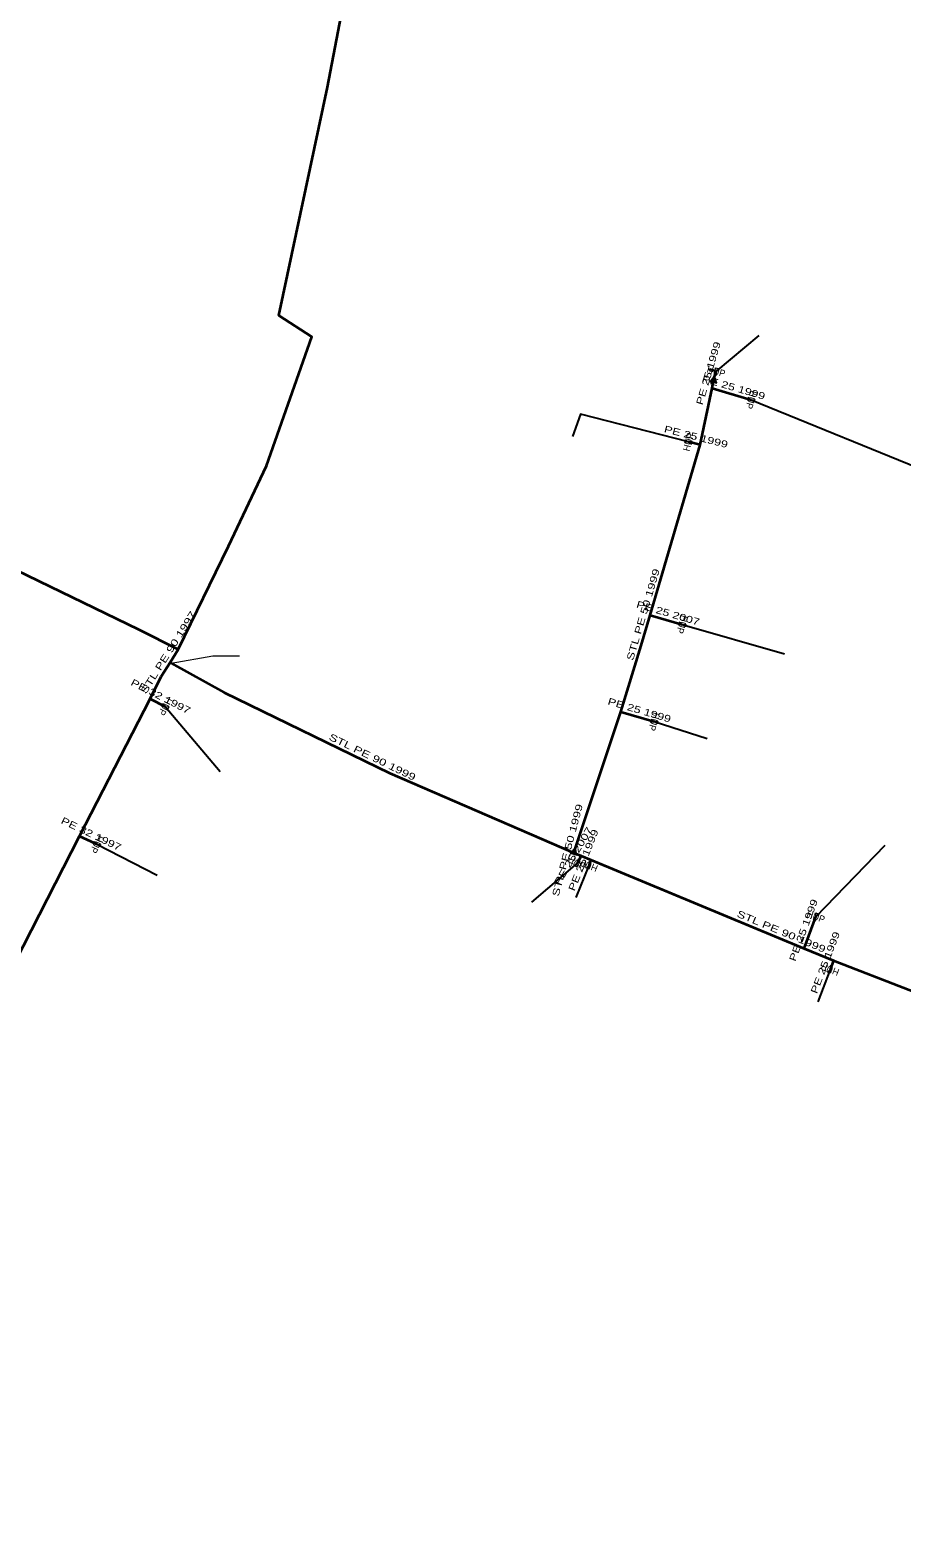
# Model space of a CAD drawing. Extents: x -737484 to -734496, y -1033882 to -1030666.
# Drawn here: x -735749 to -735623.1, y -1032392.5 to -1032174.7 of the extents above; entities that cross this region are included whole.
import ezdxf
from ezdxf.enums import TextEntityAlignment as Align

# ---------------------------------------------------------------- set-up
doc = ezdxf.new("R2010")
doc.units = 0
doc.header["$LTSCALE"] = 0.4
for name, color, linetype, lineweight in [('1', 7, 'Continuous', 13), ('22', 7, 'Continuous', 25), ('5', 7, 'Continuous', 35), ('7', 7, 'Continuous', 35)]:
    doc.layers.add(name, color=color, linetype=linetype, lineweight=lineweight)
doc.layers.add('2', color=7, linetype='Continuous')

msp = doc.modelspace()

# ---------------------------------------------------------------- linework, layer by layer
at = {"layer": '1'}
for p, q in [((-735650.461, -1032223.739), (-735650.797, -1032223.642)), ((-735649.929, -1032223.97), (-735650.409, -1032223.832))]:
    msp.add_line(p, q, dxfattribs=at)
for points in [[(-735649.982, -1032223.432), (-735649.597, -1032223.542), (-735650.258, -1032224.393), (-735649.873, -1032224.503)], [(-735650.89, -1032223.694), (-735650.931, -1032223.838), (-735650.45, -1032223.976), (-735650.409, -1032223.832)], [(-735650.89, -1032223.694), (-735650.848, -1032223.55), (-735650.368, -1032223.687), (-735650.409, -1032223.832)], [(-735650.843, -1032223.669), (-735650.822, -1032223.597), (-735650.414, -1032223.714), (-735650.434, -1032223.786)], [(-735650.833, -1032225.455), (-735649.851, -1032225.646), (-735650.151, -1032224.569)], [(-735649.991, -1032225.517), (-735650.194, -1032224.789), (-735650.655, -1032225.388)], [(-735650.236, -1032225.007), (-735650.477, -1032225.32), (-735650.13, -1032225.388)], [(-735644.322, -1032228.005), (-735644.432, -1032228.39), (-735645.283, -1032227.729), (-735645.393, -1032228.114)], [(-735654.461, -1032234.231), (-735654.364, -1032233.842), (-735653.491, -1032234.473), (-735653.394, -1032234.084)], [(-735654.304, -1032260.465), (-735654.414, -1032260.85), (-735655.265, -1032260.189), (-735655.375, -1032260.574)], [(-735728.947, -1032272.422), (-735729.129, -1032272.779), (-735729.838, -1032271.968), (-735730.02, -1032272.325)], [(-735658.352, -1032274.514), (-735658.462, -1032274.899), (-735659.313, -1032274.238), (-735659.423, -1032274.623)], [(-735738.817, -1032292.304), (-735738.986, -1032292.666), (-735739.723, -1032291.881), (-735739.892, -1032292.243)], [(-735671.002, -1032293.591), (-735670.036, -1032293.85), (-735670.26, -1032292.755)], [(-735670.167, -1032293.711), (-735670.318, -1032292.971), (-735670.82, -1032293.536)], [(-735670.376, -1032293.186), (-735670.637, -1032293.482), (-735670.296, -1032293.573)], [(-735670.096, -1032295.541), (-735670.438, -1032295.335), (-735669.581, -1032294.684), (-735669.923, -1032294.478)], [(-735668.329, -1032295.876), (-735668.7, -1032295.726), (-735667.955, -1032294.949), (-735668.326, -1032294.799)], [(-735635.553, -1032302.21), (-735635.178, -1032302.347), (-735635.895, -1032303.15), (-735635.52, -1032303.287)], [(-735633.47, -1032310.907), (-735633.843, -1032310.764), (-735633.112, -1032309.973), (-735633.485, -1032309.83)]]:
    msp.add_lwpolyline(points, close=True, dxfattribs=at)
msp.add_lwpolyline([(-735728.61, -1032266.12), (-735722.629, -1032265.037), (-735718.739, -1032265.037)], dxfattribs=at)
at = {"layer": '22'}
for p, q in [((-735649.928, -1032223.968), (-735643.699, -1032218.788)), ((-735644.858, -1032228.06), (-735614.219, -1032240.563)), ((-735654.84, -1032260.52), (-735640.05, -1032264.779)), ((-735729.484, -1032272.374), (-735721.568, -1032281.756)), ((-735658.888, -1032274.569), (-735651.24, -1032276.994)), ((-735739.356, -1032292.276), (-735730.638, -1032296.762)), ((-735635.537, -1032302.749), (-735625.538, -1032292.417)), ((-735670.01, -1032295.01), (-735676.59, -1032300.671)), ((-735668.328, -1032295.338), (-735670.179, -1032299.983)), ((-735633.478, -1032310.369), (-735635.26, -1032315.041))]:
    msp.add_line(p, q, dxfattribs=at)
msp.add_lwpolyline([(-735653.929, -1032234.159), (-735669.494, -1032230.143), (-735670.665, -1032233.365)], dxfattribs=at)
at = {"layer": '5'}
for p, q in [((-735728.779, -1032266.028), (-735727.61, -1032264.16)), ((-735670.47, -1032293.54), (-735670.39, -1032293.238))]:
    msp.add_line(p, q, dxfattribs=at)
for points in [[(-735727.61, -1032264.16), (-735720.34, -1032249.21), (-735714.85, -1032237.63), (-735708.3, -1032218.96), (-735713.1, -1032215.9), (-735706.04, -1032182.91), (-735701.19, -1032157.47), (-735702.91, -1032152.78), (-735705.8, -1032151.16), (-735736.55, -1032141.95), (-735730.97, -1032118.51), (-735729.04, -1032111.89), (-735727.47, -1032106.8), (-735722.56, -1032083.87), (-735720.82, -1032078.73), (-735717.39, -1032078.97), (-735716.966, -1032077.63)], [(-735727.61, -1032264.16), (-735733.24, -1032261.3), (-735754.23, -1032251.12), (-735765.52, -1032245.22), (-735795.64, -1032232.38), (-735827.69, -1032218.06), (-735828.419, -1032217.899)], [(-735670.39, -1032293.238), (-735663.69, -1032273.16), (-735660.75, -1032263.59), (-735659.45, -1032259.17), (-735652.22, -1032234.59), (-735650.52, -1032226.4), (-735650.247, -1032225.06)], [(-735815.73, -1032430.9), (-735815.43, -1032430.06), (-735811.41, -1032422.83), (-735808.66, -1032417.37), (-735805.75, -1032411.37), (-735798.98, -1032396.22), (-735796.46, -1032389.94), (-735789.36, -1032374.09), (-735787.3, -1032370.19), (-735782.93, -1032362.57), (-735779.46, -1032355.93), (-735774.32, -1032348.37), (-735768.24, -1032342.42), (-735754.62, -1032316.01), (-735741.84, -1032291.1), (-735731.68, -1032271.26), (-735730.05, -1032268.06), (-735728.779, -1032266.028)], [(-735728.779, -1032266.028), (-735728.61, -1032266.12), (-735720.98, -1032270.37), (-735697.03, -1032282.03), (-735670.47, -1032293.54)], [(-735670.47, -1032293.54), (-735669.395, -1032293.967), (-735668.01, -1032294.54), (-735637.23, -1032307.33), (-735632.99, -1032309.09), (-735611.11, -1032317.53)]]:
    msp.add_lwpolyline(points, dxfattribs=at)
at = {"layer": '7'}
for p, q in [((-735650.247, -1032225.06), (-735649.928, -1032223.968)), ((-735650.52, -1032226.4), (-735644.858, -1032228.06)), ((-735652.22, -1032234.59), (-735653.928, -1032234.158)), ((-735659.45, -1032259.17), (-735654.84, -1032260.52)), ((-735731.68, -1032271.26), (-735729.484, -1032272.374)), ((-735663.69, -1032273.16), (-735658.888, -1032274.569)), ((-735669.395, -1032293.967), (-735670.01, -1032295.01)), ((-735668.01, -1032294.54), (-735668.328, -1032295.338)), ((-735637.23, -1032307.33), (-735635.537, -1032302.749)), ((-735632.99, -1032309.09), (-735633.478, -1032310.369))]:
    msp.add_line(p, q, dxfattribs=at)
msp.add_lwpolyline([(-735741.84, -1032291.1), (-735740.29, -1032291.84), (-735739.355, -1032292.274)], dxfattribs=at)

# ---------------------------------------------------------------- texts
at = {"layer": '2', "width": 0.95}
for rotation, p in [(344, (-735650.0653, -1032224.4478)), (254, (-735645.3378, -1032227.9217)), (76, (-735653.442, -1032234.2785)), (254, (-735655.3198, -1032260.3817)), (243, (-735729.9295, -1032272.1465)), (254, (-735659.3678, -1032274.4307)), (245, (-735739.8076, -1032292.0622)), (149, (-735669.752, -1032294.5808)), (158, (-735668.1402, -1032294.874)), (340, (-735635.7075, -1032303.2187)), (159, (-735633.2983, -1032309.9017))]:
    msp.add_text('HUP', height=1, rotation=rotation, dxfattribs=at).set_placement(p, align=Align.CENTER)
at = {"layer": '5', "width": 1.4}
for s, rotation, p in [('STL PE 50 1999', 73.61, (-735659.9901, -1032259.2356)), ('STL PE 90 1997', 57.962, (-735728.6178, -1032264.8282)), ('STL PE 90 1999', 334.041, (-735699.7854, -1032280.1321)), ('STL PE 50 1999', 75.163, (-735670.9131, -1032293.26)), ('STL PE 90 1999', 337.436, (-735640.7059, -1032305.3439))]:
    msp.add_text(s, height=1, rotation=rotation, dxfattribs=at).set_placement(p, align=Align.CENTER)
at = {"layer": '7', "width": 1.35}
for s, rotation, p in [('PE 25 1999', 73.716, (-735650.5672, -1032224.3732)), ('PE 25 1999', 343.66, (-735647.5477, -1032226.7502)), ('PE 25 1999', 345.806, (-735652.9506, -1032233.8887)), ('PE 25 2007', 343.678, (-735657.004, -1032259.3648)), ('PE 32 1997', 333.102, (-735730.3552, -1032271.3711)), ('PE 25 1999', 343.647, (-735661.1478, -1032273.3843)), ('PE 32 1997', 334.479, (-735740.3839, -1032291.2407)), ('PE 25 2007', 59.474, (-735670.1324, -1032294.234)), ('PE 25 1999', 68.273, (-735668.6325, -1032294.7531)), ('PE 25 1999', 69.717, (-735636.8525, -1032304.8658)), ('PE 25 1999', 69.116, (-735633.7004, -1032309.5507))]:
    msp.add_text(s, height=1, rotation=rotation, dxfattribs=at).set_placement(p, align=Align.CENTER)

doc.saveas('drawing.dxf')
